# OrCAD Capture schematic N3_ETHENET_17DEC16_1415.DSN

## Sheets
1 PAGE2: size C; note: CW0057
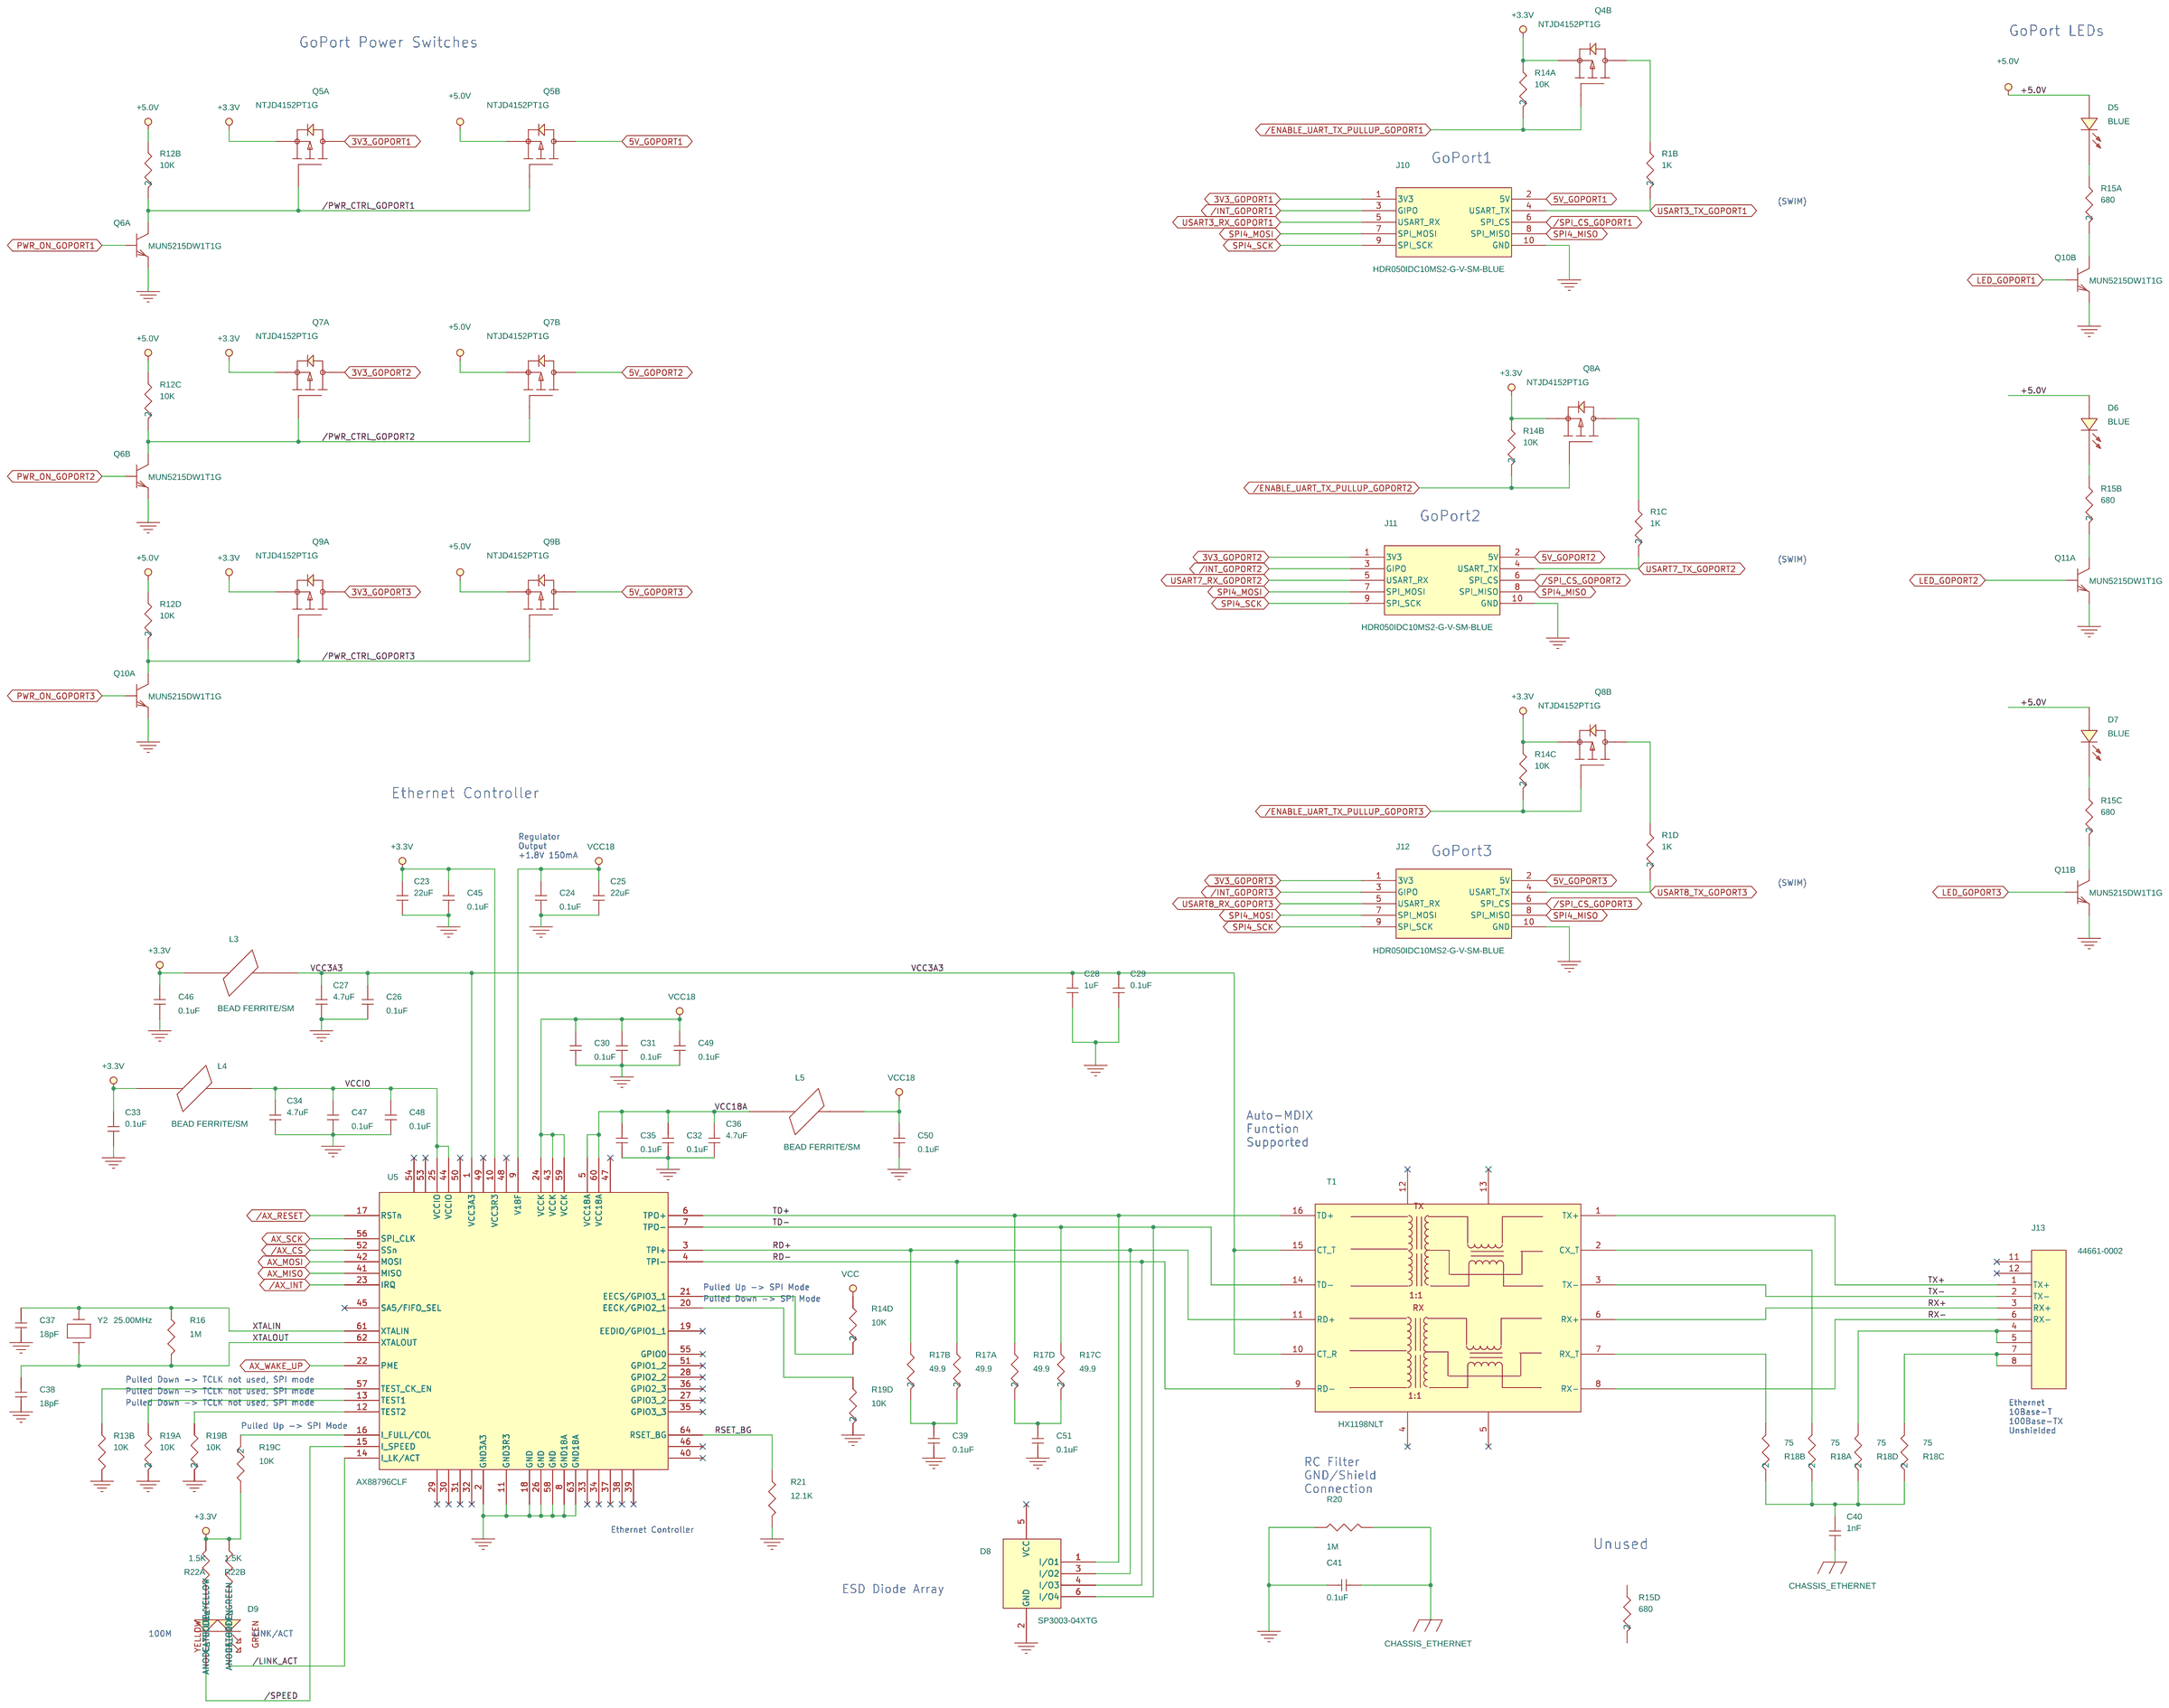
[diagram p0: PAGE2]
2 PAGE1: size C
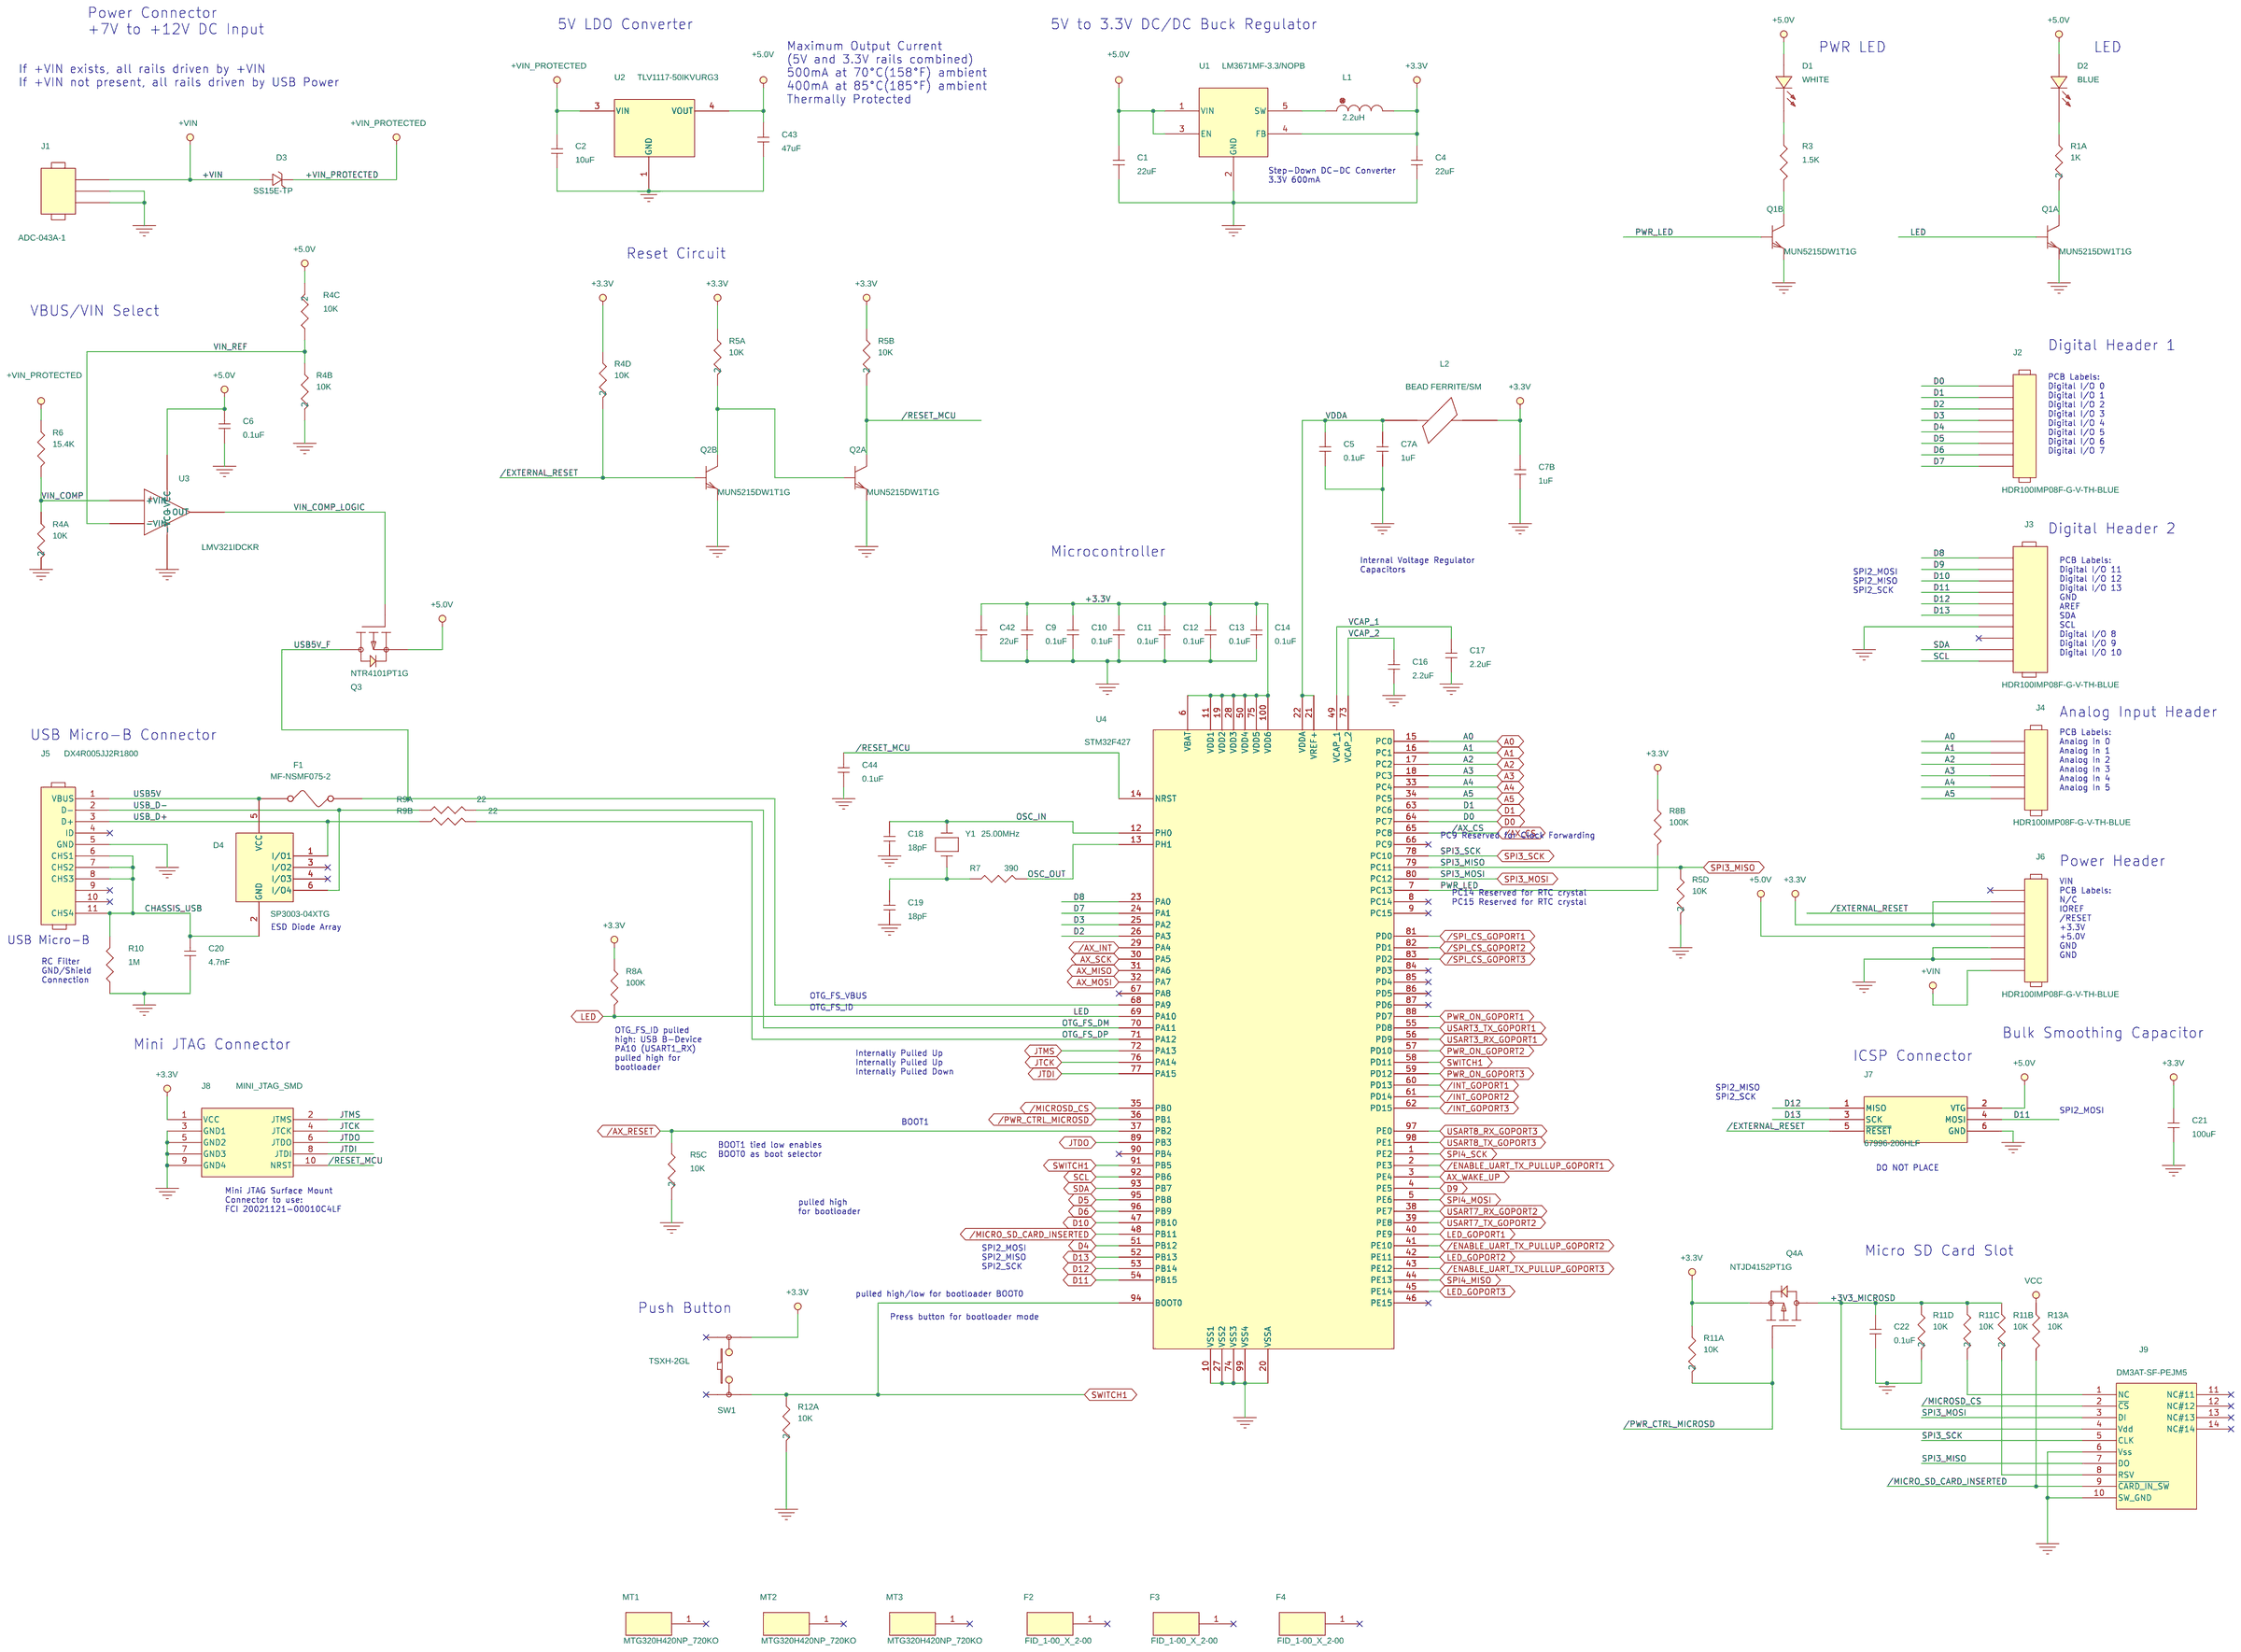
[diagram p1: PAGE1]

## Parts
sheet PAGE1
C1  22uF  [CAPC3216X180N]
C2  10uF  [CAPC2012X125N]
C4  22uF  [CAPC2012X125N]
C5  0.1uF  [CAPC1005X55N]
C6  0.1uF  [CAPC1005X55N]
C7  1uF  [GNM1M2]  (sections A,B)
C9  0.1uF  [CAP-0201]
C10  0.1uF  [CAPC1005X55N]
C11  0.1uF  [CAPC1005X55N]
C12  0.1uF  [CAPC1005X55N]
C13  0.1uF  [CAPC1005X55N]
C14  0.1uF  [CAPC1005X55N]
C16  2.2uF  [CAPC1005X55N]
C17  2.2uF  [CAPC1005X55N]
C18  18pF  [CAPC1005X55N]
C19  18pF  [CAPC1005X55N]
C20  4.7nF  [CAPC1005X55N]
C21  100uF  [CAPMP6032X280N]
C22  0.1uF  [CAPC1005X55N]
C42  22uF  [CAPC2012X125N]
C43  47uF  [F931A476MBA]
C44  0.1uF  [CAP-0201]
D1  WHITE  [LEDC2012X110N]
D2  BLUE  [LEDC2012X110N]
D3  SS15E-TP  [SS15-TP]
D4  SP3003-04XTG  [SP3003-04XTG]
F1  MF-NSMF075-2  [RESC3216X100N]
F2  FID_1-00_X_2-00  [FID_1-00_X_2-00]
F3  FID_1-00_X_2-00  [FID_1-00_X_2-00]
F4  FID_1-00_X_2-00  [FID_1-00_X_2-00]
J1  ADC-043A-1  [ADC-043A-1]
J2  HDR100IMP08F-G-V-TH-BLUE  [HDR100IMP08F-G-V-TH]
J3  HDR100IMP08F-G-V-TH-BLUE  [HDR100IMP10F-G-V-TH]
J4  HDR100IMP08F-G-V-TH-BLUE  [HDR100IMP06F-G-V-TH]
J5  DX4R005JJ2R1800  [DX4R005JJ2R1800]
J6  HDR100IMP08F-G-V-TH-BLUE  [HDR100IMP08F-G-V-TH]
J7  67996-206HLF  [67996-206HLF]
J8  MINI_JTAG_SMD  [MINI_JTAG_SMD]
J9  DM3AT-SF-PEJM5  [DM3AT-SF-PEJ]
L1  2.2uH  [LQH3NPN2R2NM0L]
L2  BEAD FERRITE/SM  [INDC1005X55N]
MT1  MTG320H420NP_720KO  [MTG320H420NP_720KO]
MT2  MTG320H420NP_720KO  [MTG320H420NP_720KO]
MT3  MTG320H420NP_720KO  [MTG320H420NP_720KO]
Q1  MUN5215DW1T1G  [MUN5215DW1T1G]  (sections A,B)
Q2  MUN5215DW1T1G  [MUN5215DW1T1G]  (sections A,B)
Q3  NTR4101PT1G  [NTR4101PT1G]
Q4  NTJD4152PT1G  [NTJD4152PT1G]  (sections A,B)
R1  1K  [RESCAV50P80X160X60-8N]  (sections A,B,C,D)
R3  1.5K  [CAPC1608X90N]
R4  10K  [RESCAV50P80X160X60-8N]  (sections A,B,C,D)
R5  10K  [RESCAV50P80X160X60-8N]  (sections A,B,C,D)
R6  15.4K  [RESC1005X40AN]
R7  390  [RESC1005X40AN]
R8  100K  [EXB24V]  (sections A,B)
R9  22  [EXB24V]  (sections A,B)
R10  1M  [RESC1005X40AN]
R11  10K  [RESCAV50P80X160X60-8N]  (sections A,B,C,D)
R12  10K  [RESCAV50P80X160X60-8N]  (sections A,B,C,D)
R13  10K  [EXB24V]  (sections A,B)
SW1  TSXH-2GL  [TSXH-2GL]
U1  LM3671MF-3.3/NOPB  [LM3671MF]
U2  TLV1117-50IKVURG3  [TLV1117-50IKVURG3]
U3  LMV321IDCKR  [LMV321IDCKR]
U4  STM32F427  [STM32F427VIT6]
Y1  25.00MHz  [ABM7]
sheet PAGE2
C23  22uF  [CAPC2012X125N]
C24  0.1uF  [CAP-0201]
C25  22uF  [CAPC2012X125N]
C26  0.1uF  [CAP-0201]
C27  4.7uF  [CAPC1608X90N]
C28  1uF  [CAPC1005X55N]
C29  0.1uF  [CAPC1005X55N]
C30  0.1uF  [CAP-0201]
C31  0.1uF  [CAP-0201]
C32  0.1uF  [CAP-0201]
C33  0.1uF  [CAPC1005X55N]
C34  4.7uF  [CAPC1608X90N]
C35  0.1uF  [CAP-0201]
C36  4.7uF  [CAPC1608X90N]
C37  18pF  [CAPC1005X55N]
C38  18pF  [CAPC1005X55N]
C39  0.1uF  [CAP-0201]
C40  1nF  [CAPC3216X180N]
C41  0.1uF  [CAPC2012X125N]
C45  0.1uF  [CAP-0201]
C46  0.1uF  [CAP-0201]
C47  0.1uF  [CAP-0201]
C48  0.1uF  [CAP-0201]
C49  0.1uF  [CAP-0201]
C50  0.1uF  [CAP-0201]
C51  0.1uF  [CAP-0201]
D5  BLUE  [LEDC1608X80N]
D6  BLUE  [LEDC1608X80N]
D7  BLUE  [LEDC1608X80N]
D8  SP3003-04XTG  [SP3003-04XTG]
D9  GREEN  [LTST-C295]
J10  HDR050IDC10MS2-G-V-SM-BLUE  [20021521-00010T1LF]
J11  HDR050IDC10MS2-G-V-SM-BLUE  [20021521-00010T1LF]
J12  HDR050IDC10MS2-G-V-SM-BLUE  [20021521-00010T1LF]
J13  44661-0002  [44661-0002]
L3  BEAD FERRITE/SM  [INDC1005X55N]
L4  BEAD FERRITE/SM  [INDC1005X55N]
L5  BEAD FERRITE/SM  [INDC1005X55N]
Q5  NTJD4152PT1G  [NTJD4152PT1G]  (sections A,B)
Q6  MUN5215DW1T1G  [MUN5215DW1T1G]  (sections A,B)
Q7  NTJD4152PT1G  [NTJD4152PT1G]  (sections A,B)
Q8  NTJD4152PT1G  [NTJD4152PT1G]  (sections A,B)
Q9  NTJD4152PT1G  [NTJD4152PT1G]  (sections A,B)
Q10  MUN5215DW1T1G  [MUN5215DW1T1G]  (sections A,B)
Q11  MUN5215DW1T1G  [MUN5215DW1T1G]  (sections A,B)
R14  10K  [RESCAV50P80X160X60-8N]  (sections A,B,C,D)
R15  680  [RESCAV50P80X160X60-8N]  (sections A,B,C,D)
R16  1M  [RESC1005X40AN]
R17  49.9  [CRA06S]  (sections A,B,C,D)
R18  75  [CRA06S]  (sections A,B,C,D)
R19  10K  [RESCAV50P80X160X60-8N]  (sections A,B,C,D)
R20  1M  [RESC1005X40AN]
R21  12.1K  [RESC1005X40AN]
R22  1.5K  [EXB24V]  (sections A,B)
T1  HX1198NLT  [HX1198NL]
U5  AX88796CLF  [AX88796CLF]
Y2  25.00MHz  [ABM7]

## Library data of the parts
C1 C2 C4-C6 C9-C14 C16-C51 = C
C7 = GNM1M2
D1 = LED_2
D2 D5-D7 = LED_1
D3 = D05AZ75_0
D4 D8 = HEADER_6_0
F1 = FUSE
F2-F4 MT1-MT3 = MOUNT_HOLE
J1 = HEADER_3
J2 J6 = HEADER_8
J3 = HEADER_10
J4 = HEADER_6
J5 = HEADER_11_0
J7 = HEADER_6_1
J8 = HEADER_10_2_v2
J9 = HEADER_10_4
L1 = L
L2-L5 = BEAD_FERRITE_SM
Q1 Q2 = MUN5215DW1T1G_3
Q3 = NDF0610_TO_1
Q4 Q5 Q7-Q9 = NTJD4152PT1G
R1 R4 R5 R11 R12 R14 R15 R17-R19 = RESCAV50P80X160X60-8N
R3 R6 R7 R10 R16 R20 R21 = R
R8 R9 R13 R22 = EXB24V
SW1 = SW_PUSHBUTTON-SPST-2_0
U1 = HEADER_5_0
U2 = LM7805_TO_2
U3 = LMV321_SO
U4 = STM32F427_0
Y1 Y2 = CRYSTAL
D9 = LED0603_GREEN_STR_1: PN1: LTST-C295KGKSKT
J10-J12 = HEADER_10_2
J13 = CONN_FPC10P_2
Q6 Q10 Q11 = MUN5215DW1T1G_0
T1 = HX1198NLT_0
U5 = AX88796CLF_1

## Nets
3V3_GOPORT1: J10.1(3V3) Q5.6(DRAIN)
3V3_GOPORT2: J11.1(3V3) Q7.6(DRAIN)
3V3_GOPORT3: J12.1(3V3) Q9.6(DRAIN)
5V_GOPORT1: J10.2(5V) Q5.3(DRAIN)
5V_GOPORT2: J11.2(5V) Q7.3(DRAIN)
5V_GOPORT3: J12.2(5V) Q9.3(DRAIN)
+3.3V: C4.1 C7.2 C9.1 C10.1 C11.1 C12.1 C13.1 C14.1 C21.1 C23.1 C33.1 C42.1 C45.1 C46.1 J6.2 J6.4 J8.1(VCC) L1.2 L2.2 L3.1 L4.1 Q4.1(SOURCE) Q4.4(SOURCE) Q5.1(SOURCE) Q7.1(SOURCE) Q8.1(SOURCE) Q8.4(SOURCE) Q9.1(SOURCE) R4.4 R5.1 R5.2 R8.1 R8.2 R11.1 R13.1 R14.1 R14.2 R14.3 R14.4 R19.3 R22.1 R22.2 SW1.2 U1.4(FB) U4.6(VBAT) U4.11(VDD1) U4.19(VDD2) U4.28(VDD3) U4.50(VDD4) U4.75(VDD5) U4.100(VDD6) U5.10(VCC3R3)
+3V3_MICROSD: C22.1 J9.4(Vdd) Q4.6(DRAIN) R11.2 R11.3 R11.4
+5.0V: C1.1 C6.1 C43.1 D1.A(ANODE) D2.A(ANODE) D5.A(ANODE) D6.A(ANODE) D7.A(ANODE) J6.5 J7.2(VTG) Q3.2(SOURCE) Q5.4(SOURCE) Q7.4(SOURCE) Q9.4(SOURCE) R4.6(2) R12.2 R12.3 R12.4 U1.1(VIN) U1.3(EN) U2.4(VOUT) U3.5(+VCC)
+VIN: D3.A(1) J1.1 J6.8
+VIN_PROTECTED: C2.1 D3.C(2) R6.1 U2.3(VIN)
VCC3A3: C26.1 C27.1 C28.1 C29.1 L3.2 T1.10(CT_R) T1.15(CT_T) U5.1(VCC3A3)
VCC18: C24.1 C25.1 C30.1 C31.1 C49.1 C50.1 L5.2 U5.9(V18F) U5.24(VCCK) U5.43(VCCK) U5.59(VCCK)
VCC18A: C32.1 C35.1 C36.1 L5.1 U5.5(VCC18A) U5.60(VCC18A)
VCCIO: C34.1 C47.1 C48.1 L4.2 U5.25(VCCIO) U5.44(VCCIO)
VDDA: C5.1 C7.1 L2.1 U4.21(VREF+) U4.22(VDDA)
VIN_COMP: R4.1 R6.2 U3.1(+VIN)
VIN_COMP_LOGIC: Q3.1(GATE) U3.4(OUT)
VIN_REF: R4.2 R4.3 U3.3(-VIN)
0: C1.2 C2.2 C4.2 C5.2 C6.2 C7.3 C7.4(3) C9.2 C10.2 C11.2 C12.2 C13.2 C14.2 C16.2 C17.2 C18.2 C19.2 C20.1 C21.2 C22.2 C23.2 C24.2 C25.2 C26.2 C27.2 C28.2 C29.2 C30.2 C31.2 C32.2 C33.2 C34.2 C35.2 C36.2 C37.2 C38.2 C39.2 C41.1 C42.2 C43.2 C44.2 C45.2 C46.2 C47.2 C48.2 C49.2 C50.2 C51.2 D8.2(GND) J1.2 J1.3 J3.7 J5.5(GND) J6.6 J6.7 J7.6(GND) J8.3(GND1) J8.5(GND2) J8.7(GND3) J8.9(GND4) J9.6(Vss) J9.10(SW_GND) J10.10(GND) J11.10(GND) J12.10(GND) Q1.1(e) Q1.4(e) Q2.1(e) Q2.4(e) Q6.1(e) Q6.4(e) Q10.1(e) Q10.4(e) Q11.1(e) Q11.4(e) R4.7(2) R4.8(2) R5.5(2) R5.6(2) R10.1 R11.5(2) R12.8(2) R13.3(2) R19.5(2) R19.7(2) R19.8(2) R20.1 R21.2 U1.2(GND) U2.1(GND) U3.2(-VCC) U4.10(VSS1) U4.20(VSSA) U4.27(VSS2) U4.74(VSS3) U4.99(VSS4) U5.2(GND3A3) U5.8(GND18A) U5.11(GND3R3) U5.18(GND) U5.26(GND) U5.58(GND) U5.63(GND18A)
/AX_CS: U4.65(PC8) U5.52(SSn)
/AX_INT: U4.29(PA4) U5.23(IRQ)
/AX_RESET: R5.3 U4.37(PB2) U5.17(RSTn)
/ENABLE_UART_TX_PULLUP_GOPORT1: Q4.5(GATE) R14.8(2) U4.2(PE3)
/ENABLE_UART_TX_PULLUP_GOPORT2: Q8.2(GATE) R14.7(2) U4.41(PE10)
/ENABLE_UART_TX_PULLUP_GOPORT3: Q8.5(GATE) R14.6(2) U4.43(PE12)
/EXTERNAL_RESET: J6.3 J7.5(~{RESET}) Q2.5(b) R4.5(2)
/INT_GOPORT1: J10.3(GIPO) U4.60(PD13)
/INT_GOPORT2: J11.3(GIPO) U4.61(PD14)
/INT_GOPORT3: J12.3(GIPO) U4.62(PD15)
/LINK_ACT: D9.3(CATHODE_GREEN) U5.14(I_LK/ACT)
/MICRO_SD_CARD_INSERTED: J9.9(~{CARD_IN_SW}) R13.4(2) U4.48(PB11)
/MICROSD_CS: J9.2(~{CS}) U4.35(PB0)
/PWR_CTRL_GOPORT1: Q5.2(GATE) Q5.5(GATE) Q6.3(c) R12.7(2)
/PWR_CTRL_GOPORT2: Q6.6(c) Q7.2(GATE) Q7.5(GATE) R12.6(2)
/PWR_CTRL_GOPORT3: Q9.2(GATE) Q9.5(GATE) Q10.3(c) R12.5(2)
/PWR_CTRL_MICROSD: Q4.2(GATE) R11.8(2) U4.36(PB1)
/RESET_MCU: C44.1 J8.10(NRST) Q2.6(c) R5.7(2) U4.14(NRST)
/SPEED: D9.4(CATHODE_YELLOW) U5.15(I_SPEED)
/SPI_CS_GOPORT1: J10.6(SPI_CS) U4.81(PD0)
/SPI_CS_GOPORT2: J11.6(SPI_CS) U4.82(PD1)
/SPI_CS_GOPORT3: J12.6(SPI_CS) U4.83(PD2)
A0: J4.1 U4.15(PC0)
A1: J4.2 U4.16(PC1)
A2: J4.3 U4.17(PC2)
A3: J4.4 U4.18(PC3)
A4: J4.5 U4.33(PC4)
A5: J4.6 U4.34(PC5)
AX_MISO: U4.31(PA6) U5.41(MISO)
AX_MOSI: U4.32(PA7) U5.42(MOSI)
AX_SCK: U4.30(PA5) U5.56(SPI_CLK)
AX_WAKE_UP: U4.3(PE4) U5.22(PME)
CHASSIS_ETHERNET: C40.2 C41.2 R20.2
CHASSIS_USB: C20.2 D4.2(GND) J5.6(CHS1) J5.7(CHS2) J5.8(CHS3) J5.11(CHS4) R10.2
D0: J2.1 U4.64(PC7)
D1: J2.2 U4.63(PC6)
D2: J2.3 U4.26(PA3)
D3: J2.4 U4.25(PA2)
D4: J2.5 U4.51(PB12)
D5: J2.6 U4.95(PB8)
D6: J2.7 U4.96(PB9)
D7: J2.8 U4.24(PA1)
D8: J3.1 U4.23(PA0)
D9: J3.2 U4.4(PE5)
D10: J3.3 U4.47(PB10)
D11: J3.4 J7.4(MOSI) U4.54(PB15)
D12: J3.5 J7.1(MISO) U4.53(PB14)
D13: J3.6 J7.3(SCK) U4.52(PB13)
JTCK: J8.4(JTCK) U4.76(PA14)
JTDI: J8.8(JTDI) U4.77(PA15)
JTDO: J8.6(JTDO) U4.89(PB3)
JTMS: J8.2(JTMS) U4.72(PA13)
LED: Q1.2(b) R8.4(2) U4.69(PA10)
LED_GOPORT1: Q10.2(b) U4.40(PE9)
LED_GOPORT2: Q11.5(b) U4.42(PE11)
LED_GOPORT3: Q11.2(b) U4.45(PE14)
OSC_IN: C18.1 U4.12(PH0) Y1.2
OSC_OUT: R7.2 U4.13(PH1)
OTG_FS_DM: R9.4(2) U4.70(PA11)
OTG_FS_DP: R9.3(2) U4.71(PA12)
PWR_LED: Q1.5(b) R8.3(2) U4.7(PC13)
PWR_ON_GOPORT1: Q6.5(b) U4.88(PD7)
PWR_ON_GOPORT2: Q6.2(b) U4.57(PD10)
PWR_ON_GOPORT3: Q10.5(b) U4.59(PD12)
RD+: D8.3(I/O2) R17.2 T1.11(RD+) U5.3(TPI+)
RD-: D8.4(I/O3) R17.1 T1.9(RD-) U5.4(TPI-)
RSET_BG: R21.1 U5.64(RSET_BG)
RX+: J13.3(RX+) T1.6(RX+)
RX-: J13.6(RX-) T1.8(RX-)
SCL: J3.10 U4.92(PB6)
SDA: J3.9 U4.93(PB7)
SPI3_MISO: J9.7(DO) R5.4 U4.79(PC11)
SPI3_MOSI: J9.3(DI) U4.80(PC12)
SPI3_SCK: J9.5(CLK) U4.78(PC10)
SPI4_MISO: J10.8(SPI_MISO) J11.8(SPI_MISO) J12.8(SPI_MISO) U4.44(PE13)
SPI4_MOSI: J10.7(SPI_MOSI) J11.7(SPI_MOSI) J12.7(SPI_MOSI) U4.5(PE6)
SPI4_SCK: J10.9(SPI_SCK) J11.9(SPI_SCK) J12.9(SPI_SCK) U4.1(PE2)
SWITCH1: R12.1 SW1.4 U4.58(PD11) U4.91(PB5) U4.94(BOOT0)
TD+: D8.1(I/O1) R17.4 T1.16(TD+) U5.6(TPO+)
TD-: D8.6(I/O4) R17.3 T1.14(TD-) U5.7(TPO-)
TX+: J13.1(TX+) T1.1(TX+)
TX-: J13.2(TX-) T1.3(TX-)
USART3_RX_GOPORT1: J10.5(USART_RX) U4.56(PD9)
USART3_TX_GOPORT1: J10.4(USART_TX) R1.7(2) U4.55(PD8)
USART7_RX_GOPORT2: J11.5(USART_RX) U4.38(PE7)
USART7_TX_GOPORT2: J11.4(USART_TX) R1.6(2) U4.39(PE8)
USART8_RX_GOPORT3: J12.5(USART_RX) U4.97(PE0)
USART8_TX_GOPORT3: J12.4(USART_TX) R1.5(2) U4.98(PE1)
USB5V: D4.5(VCC) F1.1 J5.1(VBUS)
USB5V_F: F1.2 Q3.3(DRAIN) U4.68(PA9)
USB_D+: D4.1(I/O1) J5.3(D+) R9.2
USB_D-: D4.6(I/O4) J5.2(D-) R9.1
VCAP_1: C17.1 U4.49(VCAP_1)
VCAP_2: C16.1 U4.73(VCAP_2)
XTALIN: C37.1 R16.1 U5.61(XTALIN) Y2.2
XTALOUT: C38.1 R16.2 U5.62(XTALOUT) Y2.1
N332853: Q2.2(b) Q2.3(c) R5.8(2)
N332873: L1.1 U1.5(SW)
N332891: D2.C(CATHODE) R1.1
N333149: Q1.6(c) R1.8(2)
N333173: D1.C(CATHODE) R3.1
N333175: Q1.3(c) R3.2
N333299: C19.1 R7.1 Y1.1
N333445: J9.1(NC) R11.6(2)
N333449: J9.8(RSV) R11.7(2)
N337920: Q10.6(c) R15.8(2)
N337928: D5.C(CATHODE) R15.1
N337930: Q11.3(c) R15.7(2)
N337938: D6.C(CATHODE) R15.2
N337940: Q11.6(c) R15.6(2)
N337948: D7.C(CATHODE) R15.3
N337960: Q4.3(DRAIN) R1.2
N337994: Q8.6(DRAIN) R1.3
N338028: Q8.3(DRAIN) R1.4
N338320: R19.2 U5.12(TEST2)
N338324: R19.1 U5.13(TEST1)
N338328: R13.2 U5.57(TEST_CK_EN)
N338332: R19.6(2) U5.16(I_FULL/COL)
N338402: R14.5(2) U5.21(EECS/GPIO3_1)
N338408: R19.4 U5.20(EECK/GPIO2_1)
N338436: C51.1 R17.5(2) R17.6(2)
N338444: C39.1 R17.7(2) R17.8(2)
N338526: J13.4 J13.5 R18.4
N338532: J13.7 J13.8 R18.3
N338540: R18.1 T1.2(CX_T)
N338544: R18.2 T1.7(RX_T)
N338558: C40.1 R18.5(2) R18.6(2) R18.7(2) R18.8(2)
N357247: D9.2(ANODE_YELLOW) R22.3(2)
N357249: D9.1(ANODE_GREEN) R22.4(2)

Not connected (* = marked no-connect by the designer): D4 3(I/O2)* 4(I/O3)*; D8 5(VCC)*; F2 1*; F3 1*; F4 1*; J3 8*; J5 4(ID)* 9* 10*; J6 1*; J9 11(NC#11)* 12(NC#12)* 13(NC#13)* 14(NC#14)*; J13 11* 12*; MT1 1*; MT2 1*; MT3 1*; R15 4 5(2); SW1 1* 3*; T1 4* 5* 12* 13*; U4 8(PC14)* 9(PC15)* 46(PE15)* 66(PC9)* 67(PA8)* 84(PD3)* 85(PD4)* 86(PD5)* 87(PD6)* 90(PB4)*; U5 19(EEDIO/GPIO1_1)* 27(GPIO3_2)* 28(GPIO2_2)* 29* 30* 31* 32* 33* 34* 35(GPIO3_3)* 36(GPIO2_3)* 37* 38* 39* 40* 45(SA5/FIFO_SEL)* 46* 47* 48* 49* 50* 51(GPIO1_2)* 53* 54* 55(GPIO0)*

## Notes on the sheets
sheet 1
- GoPort LEDs
- GoPort Power Switches
- GoPort1
- (SWIM)
- GoPort2
- (SWIM)
- Ethernet Controller
- Regulator
  Output
  +1.8V 150mA
- GoPort3
- (SWIM)
- Auto-MDIX
  Function
  Supported
- Pulled Up -> SPI Mode
- Pulled Down -> SPI Mode
- Pulled Down -> TCLK not used, SPI mode
- Pulled Down -> TCLK not used, SPI mode
- Pulled Down -> TCLK not used, SPI mode
- Ethernet
  10Base-T
  100Base-TX
  Unshielded
- Pulled Up -> SPI Mode
- RC Filter
  GND/Shield
  Connection
- Ethernet Controller
- Unused
- ESD Diode Array
- 100M
- LINK/ACT
sheet 2
- Power Connector
  +7V to +12V DC Input
- 5V LDO Converter
- 5V to 3.3V DC/DC Buck Regulator
- Maximum Output Current
  (5V and 3.3V rails combined)
  500mA at 70°C(158°F) ambient
  400mA at 85°C(185°F) ambient
  Thermally Protected
- PWR LED
- LED
- If +VIN exists, all rails driven by +VIN
  If +VIN not present, all rails driven by USB Power
- Step-Down DC-DC Converter
  3.3V 600mA
- Reset Circuit
- VBUS/VIN Select
- Digital Header 1
- PCB Labels:
  Digital I/O 0
  Digital I/O 1
  Digital I/O 2
  Digital I/O 3
  Digital I/O 4
  Digital I/O 5
  Digital I/O 6
  Digital I/O 7
- Digital Header 2
- Microcontroller
- Internal Voltage Regulator
  Capacitors
- PCB Labels:
  Digital I/O 11
  Digital I/O 12
  Digital I/O 13
  GND
  AREF
  SDA
  SCL
  Digital I/O 8
  Digital I/O 9
  Digital I/O 10
- SPI2_MOSI
  SPI2_MISO
  SPI2_SCK
- Analog Input Header
- USB Micro-B Connector
- PCB Labels:
  Analog In 0
  Analog In 1
  Analog In 2
  Analog In 3
  Analog In 4
  Analog In 5
- PC9 Reserved for Clock Forwarding
- Power Header
- VIN
  PCB Labels:
  N/C
  IOREF
  /RESET
  +3.3V
  +5.0V
  GND
  GND
- PC14 Reserved for RTC crystal
  PC15 Reserved for RTC crystal
- ESD Diode Array
- USB Micro-B
- RC Filter
  GND/Shield
  Connection
- OTG_FS_VBUS
- OTG_FS_ID
- OTG_FS_ID pulled
  high: USB B-Device
  PA10 (USART1_RX)
  pulled high for
  bootloader
- Bulk Smoothing Capacitor
- Mini JTAG Connector
- Internally Pulled Up
  Internally Pulled Up
  Internally Pulled Down
- ICSP Connector
- SPI2_MISO
  SPI2_SCK
- SPI2_MOSI
- BOOT1
- BOOT1 tied low enables
  BOOT0 as boot selector
- DO NOT PLACE
- Mini JTAG Surface Mount
  Connector to use:
  FCI 20021121-00010C4LF
- pulled high
  for bootloader
- SPI2_MOSI
  SPI2_MISO
  SPI2_SCK
- Micro SD Card Slot
- pulled high/low for bootloader BOOT0
- Push Button
- Press button for bootloader mode
